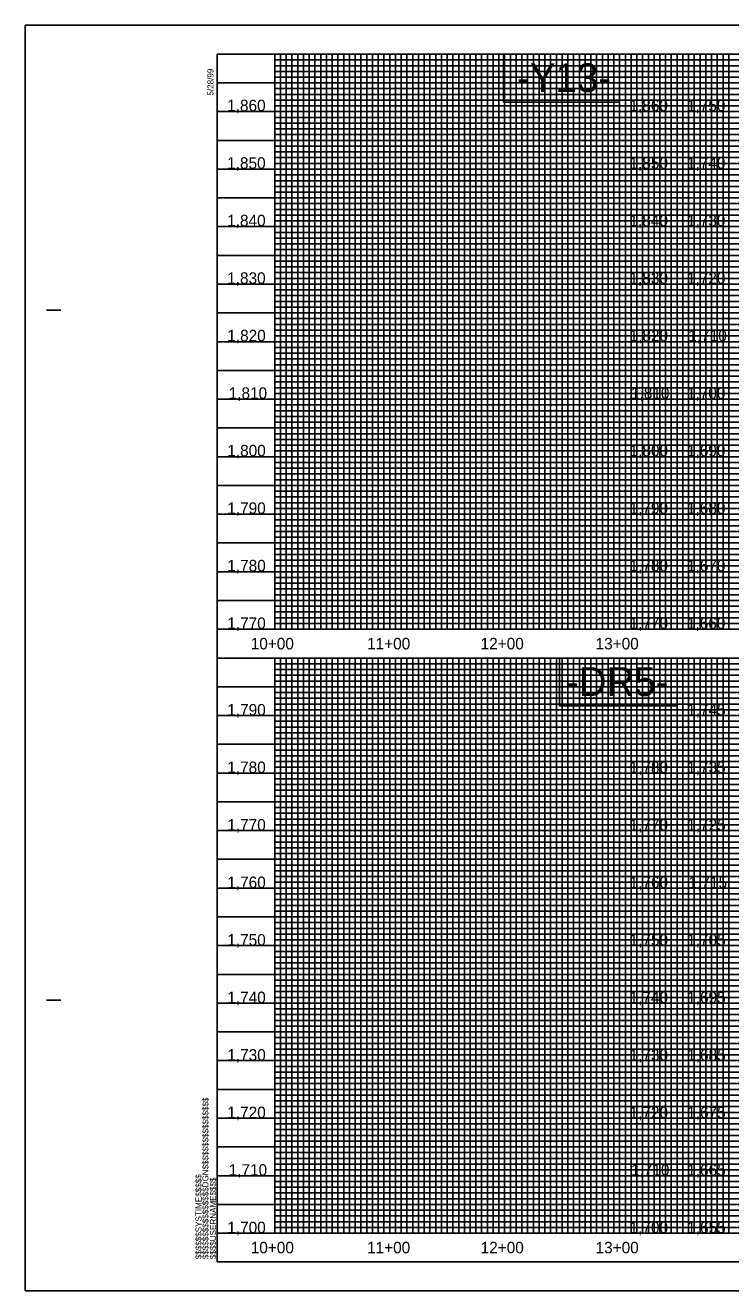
# Model space of a CAD drawing. Extents: x 505602 to 507286, y 483109 to 484209.
# Drawn here: x 505602 to 506216, y 483109 to 484209 of the extents above; entities that cross this region are included whole.
import ezdxf

# ---------------------------------------------------------------- set-up
doc = ezdxf.new("R2010")
doc.units = 0
for name, color, linetype in [('Exist Vertical Profile Vertical Axis Label', 7, 'Continuous'), ('Old_Level_1', 7, 'Continuous'), ('Prop Grid Mask', 7, 'Continuous'), ('Sheet Layout Profile Border Port 1', 7, 'Continuous'), ('Sheet Layout Profile Border Port 2', 7, 'Continuous'), ('Sheet Plot Border Outside CELL', 7, 'Continuous'), ('Sheet Profile CELL', 7, 'Continuous'), ('Sheet Profile Grid Major CELL', 7, 'Continuous'), ('Sheet Profile Grid Middle CELL', 7, 'Continuous'), ('Sheet Profile Grid Minor CELL', 7, 'Continuous')]:
    doc.layers.add(name, color=color, linetype=linetype)

msp = doc.modelspace()

# ---------------------------------------------------------------- linework, layer by layer
at = {"layer": 'Prop Grid Mask'}
for points in [[(506119.1, 484183.7), (506018.1, 484183.7), (506018.1, 484142), (506119.1, 484142)], [(506169.1, 483658.7), (506066.8, 483658.7), (506066.8, 483617), (506169.1, 483617)]]:
    msp.add_lwpolyline(points, close=True, dxfattribs=at)
at = {"layer": 'Sheet Layout Profile Border Port 1'}
msp.add_lwpolyline([(505769.1, 484183.7), (506169.1, 484183.7), (506169.1, 483683.7), (505769.1, 483683.7)], close=True, dxfattribs=at)
at = {"layer": 'Sheet Layout Profile Border Port 2'}
for points in [[(505819.1, 483658.7), (506169.1, 483658.7), (506169.1, 483158.7), (505819.1, 483158.7)], [(506169.1, 483658.7), (507219.1, 483658.7), (507219.1, 483158.7), (506169.1, 483158.7)]]:
    msp.add_lwpolyline(points, close=True, dxfattribs=at)
at = {"layer": 'Sheet Plot Border Outside CELL'}
msp.add_lwpolyline([(505602.1, 483108.7), (507286.1, 483108.7), (507286.1, 484208.7), (505602.1, 484208.7)], close=True, dxfattribs=at)
at = {"layer": 'Sheet Profile CELL'}
for p, q in [((506169.1, 483683.7), (506169.1, 484183.7)), ((505620.6, 483961.2), (505633.1, 483961.2)), ((505769.1, 483683.7), (507269.1, 483683.7)), ((505769.1, 483658.7), (507269.1, 483658.7)), ((506169.1, 483158.7), (506169.1, 483658.7)), ((505620.6, 483361.2), (505633.1, 483361.2)), ((507269.1, 483158.7), (505769.1, 483158.7)), ((505769.1, 483133.7), (507269.1, 483133.7)), ((505769.1, 483133.7), (505769.1, 483133.7)), ((505769.1, 483133.7), (505769.1, 483133.7)), ((505769.1, 483133.7), (505769.1, 483133.7)), ((505769.1, 483133.7), (505769.1, 483133.7)), ((505769.1, 483133.7), (505769.1, 483133.7)), ((505769.1, 483133.7), (505769.1, 483133.7)), ((505769.1, 483133.7), (505769.1, 483133.7))]:
    msp.add_line(p, q, dxfattribs=at)
msp.add_lwpolyline([(507269.1, 484183.7), (505769.1, 484183.7), (505769.1, 483133.7), (507269.1, 483133.7)], close=True, dxfattribs=at)
msp.add_lwpolyline([(505806.6, 483133.7), (505806.6, 483133.7)], dxfattribs=at)
at = {"layer": 'Sheet Profile Grid Major CELL'}
for points in [[(505819.1, 484183.7), (505819.1, 483683.7), (505869.1, 483683.7), (505869.1, 484183.7), (505919.1, 484183.7), (505919.1, 483683.7), (505969.1, 483683.7), (505969.1, 484183.7), (506019.1, 484183.7), (506019.1, 483683.7), (506069.1, 483683.7), (506069.1, 484183.7), (506119.1, 484183.7), (506119.1, 483683.7), (506169.1, 483683.7), (506169.1, 484183.7), (506219.1, 484183.7)], [(505769.1, 484133.7), (507069.1, 484133.7)], [(507069.1, 484083.7), (505769.1, 484083.7), (505769.1, 484033.7), (507069.1, 484033.7)], [(507269.1, 483983.7), (505769.1, 483983.7), (505769.1, 483933.7), (507269.1, 483933.7)], [(507269.1, 483883.7), (505769.1, 483883.7), (505769.1, 483833.7), (507269.1, 483833.7)], [(507269.1, 483783.7), (505769.1, 483783.7), (505769.1, 483783.7), (505769.1, 483733.7), (507269.1, 483733.7)], [(505769.1, 483658.7), (505769.1, 483158.7), (505819.1, 483158.7), (505819.1, 483658.7), (505869.1, 483658.7), (505869.1, 483158.7), (505919.1, 483158.7), (505919.1, 483658.7), (505969.1, 483658.7), (505969.1, 483158.7), (506019.1, 483158.7), (506019.1, 483658.7), (506069.1, 483658.7), (506069.1, 483158.7), (506119.1, 483158.7), (506119.1, 483658.7), (506169.1, 483658.7), (506169.1, 483158.7), (506219.1, 483158.7)], [(505819.1, 483658.7), (505819.1, 483158.7), (505869.1, 483158.7), (505869.1, 483658.7), (505919.1, 483658.7), (505919.1, 483158.7), (505969.1, 483158.7), (505969.1, 483658.7), (506019.1, 483658.7), (506019.1, 483158.7), (506069.1, 483158.7), (506069.1, 483658.7), (506119.1, 483658.7), (506119.1, 483158.7), (506169.1, 483158.7), (506169.1, 483658.7), (506219.1, 483658.7)], [(507269.1, 483608.7), (505769.1, 483608.7)], [(507269.1, 483558.7), (505769.1, 483558.7), (505769.1, 483508.7), (507269.1, 483508.7)], [(507269.1, 483458.7), (505769.1, 483458.7), (505769.1, 483408.7), (507269.1, 483408.7)], [(507269.1, 483358.7), (505769.1, 483358.7), (505769.1, 483308.7), (507269.1, 483308.7)], [(507269.1, 483258.7), (505769.1, 483258.7), (505769.1, 483258.7), (505769.1, 483208.7), (507269.1, 483208.7)], [(507269.1, 483158.7), (505769.1, 483158.7)]]:
    msp.add_lwpolyline(points, dxfattribs=at)
at = {"layer": 'Sheet Profile Grid Middle CELL'}
msp.add_line((505769.1, 484158.7), (507069, 484158.7), dxfattribs=at)
msp.add_line((505769.1, 484158.7), (507069, 484158.7), dxfattribs=at)
for points in [[(505844.1, 484183.7), (505844.1, 483683.7), (505894.1, 483683.7), (505894.1, 484183.7), (505944.1, 484183.7), (505944.1, 483683.7), (505994.1, 483683.7), (505994.1, 484183.7), (506044.1, 484183.7), (506044.1, 483683.7), (506094.1, 483683.7), (506094.1, 484183.7), (506144.1, 484183.7), (506144.1, 483683.7), (506194.1, 483683.7), (506194.1, 484183.7), (506244.1, 484183.7)], [(507069.1, 484108.7), (505769.1, 484108.7), (505769.1, 484058.7), (507069.1, 484058.7)], [(507269.1, 484008.7), (505769.1, 484008.7), (505769.1, 483958.7), (507094.1, 483958.7)], [(507269.1, 483908.7), (505769.1, 483908.7), (505769.1, 483858.7), (507269.1, 483858.7)], [(507269.1, 483808.7), (505769.1, 483808.7), (505769.1, 483758.7), (507269.1, 483758.7)], [(507269.1, 483708.7), (505769.1, 483708.7)], [(505794.1, 483658.7), (505844.1, 483658.7), (505844.1, 483158.7), (505894.1, 483158.7), (505894.1, 483658.7), (505944.1, 483658.7), (505944.1, 483158.7), (505994.1, 483158.7), (505994.1, 483658.7), (506044.1, 483658.7), (506044.1, 483158.7), (506094.1, 483158.7), (506094.1, 483658.7), (506144.1, 483658.7), (506144.1, 483158.7), (506194.1, 483158.7), (506194.1, 483658.7), (506244.1, 483658.7)], [(505769.1, 483633.7), (507269.1, 483633.7)], [(507269.1, 483583.7), (505769.1, 483583.7), (505769.1, 483533.7), (507269.1, 483533.7)], [(507269.1, 483483.7), (505769.1, 483483.7), (505769.1, 483433.7), (507269.1, 483433.7)], [(507269.1, 483383.7), (505769.1, 483383.7), (505769.1, 483333.7), (507269.1, 483333.7)], [(507269.1, 483283.7), (505769.1, 483283.7), (505769.1, 483233.7), (507269.1, 483233.7)], [(507269.1, 483183.7), (505769.1, 483183.7)]]:
    msp.add_lwpolyline(points, dxfattribs=at)
at = {"layer": 'Sheet Profile Grid Minor CELL'}
for p, q in [((505819.1, 484178.7), (507069.1, 484178.7)), ((505819.1, 484173.7), (505819.1, 484173.7)), ((507069.1, 484173.7), (505819.1, 484173.4)), ((505819.1, 484168.7), (507069.1, 484168.7)), ((507069, 484048.7), (505819.1, 484048.7)), ((507069.1, 484043.7), (505819.1, 484043.7)), ((507069.1, 484038.7), (505819.1, 484038.7)), ((505819.1, 484028.7), (507069.1, 484028.7)), ((507069.1, 484023.7), (505819.1, 484023.7)), ((505819.1, 484018.7), (507219.1, 484018.7)), ((507219.1, 483998.7), (505819.1, 483998.7)), ((505819.1, 483993.7), (507219.1, 483993.7)), ((507219.1, 483973.7), (505819.1, 483973.7)), ((505819.1, 483968.7), (507219.1, 483968.7)), ((507219.1, 483948.7), (505819.1, 483948.7)), ((505819.1, 483943.7), (507219.1, 483943.7)), ((507219.1, 483938.7), (505819.1, 483938.7)), ((505819.1, 483928.7), (507219.1, 483928.7)), ((507219.1, 483923.7), (505819.1, 483923.7)), ((505819.1, 483918.7), (507219.1, 483918.7)), ((507219.1, 483913.7), (505819.1, 483913.7)), ((505819.1, 483903.7), (507219.1, 483903.7)), ((507219.1, 483898.7), (505819.1, 483898.7)), ((505819.1, 483893.7), (507219.1, 483893.7)), ((507219.1, 483888.7), (505819.1, 483888.7)), ((505819.1, 483878.7), (507219.1, 483878.7)), ((507219.1, 483873.7), (505819.1, 483873.7)), ((505819.1, 483868.7), (507219.1, 483868.7)), ((507219.1, 483863.7), (505819.1, 483863.7)), ((505819.1, 483853.7), (507219.1, 483853.7)), ((507219.1, 483848.7), (505819.1, 483848.7)), ((505819.1, 483843.7), (507219.1, 483843.7)), ((507219.1, 483838.7), (505819.1, 483838.7)), ((505819.1, 483828.7), (507219.1, 483828.7)), ((507219.1, 483823.7), (505819.1, 483823.7)), ((505819.1, 483818.7), (507219.1, 483818.7)), ((507219.1, 483813.7), (505819.1, 483813.7)), ((505819.1, 483803.7), (507219.1, 483803.7)), ((507219.1, 483798.7), (505819.1, 483798.7)), ((507219.1, 483793.7), (505819.1, 483793.7)), ((507219.1, 483788.7), (505819.1, 483788.7)), ((505819.1, 483778.7), (507219.1, 483778.7)), ((507219.1, 483773.7), (505819.1, 483773.7)), ((505819.1, 483768.7), (507219.1, 483768.7)), ((507219.1, 483763.7), (505819.1, 483763.7)), ((505819.1, 483753.7), (507219.1, 483753.7)), ((507219.1, 483748.7), (505819.1, 483748.7)), ((505819.1, 483743.7), (507219.1, 483743.7)), ((507219.1, 483738.7), (505819.1, 483738.7)), ((505819.1, 483728.7), (507219.1, 483728.7)), ((507219.1, 483723.7), (505819.1, 483723.7)), ((505819.1, 483718.7), (507219.1, 483718.7)), ((507219.1, 483713.7), (505819.1, 483713.7)), ((505819.1, 483703.7), (507219.1, 483703.7)), ((507219.1, 483698.7), (505819.1, 483698.7)), ((505819.1, 483693.7), (507219.1, 483693.7)), ((505819.1, 483653.7), (507219.1, 483653.7)), ((507219.1, 483648.7), (505819.1, 483648.7)), ((505819.1, 483643.7), (507219.1, 483643.7)), ((507219.1, 483638.7), (505819.1, 483638.7)), ((505819.1, 483628.7), (507219.1, 483628.7)), ((507219.1, 483623.7), (505819.1, 483623.7)), ((505819.1, 483618.7), (507219.1, 483618.7)), ((507219.1, 483613.7), (505819.1, 483613.7)), ((505819.1, 483603.7), (507219.1, 483603.7)), ((507219.1, 483598.7), (505819.1, 483598.7)), ((505819.1, 483593.7), (507219.1, 483593.7)), ((507219.1, 483588.7), (505819.1, 483588.7)), ((505819.1, 483578.7), (507219.1, 483578.7)), ((507219.1, 483573.7), (505819.1, 483573.7)), ((505819.1, 483568.7), (507219.1, 483568.7)), ((507219.1, 483563.7), (505819.1, 483563.7)), ((505819.1, 483553.7), (507219.1, 483553.7)), ((507219.1, 483548.7), (505819.1, 483548.7)), ((505819.1, 483543.7), (507219.1, 483543.7)), ((507219.1, 483538.7), (505819.1, 483538.7)), ((505819.1, 483528.7), (507219.1, 483528.7)), ((507219.1, 483523.7), (505819.1, 483523.7)), ((505819.1, 483518.7), (507219.1, 483518.7)), ((507219.1, 483513.7), (505819.1, 483513.7)), ((505819.1, 483503.7), (507219.1, 483503.7)), ((507219.1, 483498.7), (505819.1, 483498.7)), ((505819.1, 483493.7), (507219.1, 483493.7)), ((507219.1, 483488.7), (505819.1, 483488.7)), ((505819.1, 483478.7), (507219.1, 483478.7)), ((507219.1, 483473.7), (505819.1, 483473.7)), ((505819.1, 483468.7), (507219.1, 483468.7)), ((507219.1, 483463.7), (505819.1, 483463.9)), ((505819.1, 483453.7), (507219.1, 483453.7)), ((507219.1, 483448.7), (505819.1, 483448.7)), ((505819.1, 483443.7), (507219.1, 483443.7)), ((507219.1, 483438.7), (505819.1, 483438.7)), ((505819.1, 483428.7), (507219.1, 483428.7)), ((507219.1, 483423.7), (505819.1, 483423.7)), ((505819.1, 483418.7), (507219.1, 483418.7)), ((507219.1, 483413.7), (505819.1, 483413.7)), ((505819.1, 483403.7), (507219.1, 483403.7)), ((507219.1, 483398.7), (505819.1, 483398.7)), ((505819.1, 483393.7), (507219.1, 483393.7)), ((507219.1, 483388.7), (505819.1, 483388.7)), ((505819.1, 483378.7), (507219.1, 483378.7)), ((507219.1, 483373.7), (505819.1, 483373.7)), ((505819.1, 483368.7), (507219.1, 483368.7)), ((507219.1, 483363.7), (505819.1, 483363.7)), ((505819.1, 483353.7), (507219.1, 483353.7)), ((507219.1, 483348.7), (505819.1, 483348.7)), ((505819.1, 483343.7), (507219.1, 483343.7)), ((507219.1, 483338.7), (505819.1, 483338.7)), ((505819.1, 483328.7), (507219.1, 483328.7)), ((507219.1, 483323.7), (505819.1, 483323.7)), ((505819.1, 483318.7), (507219.1, 483318.7)), ((507219.1, 483313.7), (505819.1, 483313.7)), ((505819.1, 483303.7), (507219.1, 483303.7)), ((507219.1, 483298.7), (505819.1, 483298.7)), ((505819.1, 483293.7), (507219.1, 483293.7)), ((507219.1, 483288.7), (505819.1, 483288.7)), ((505819.1, 483278.7), (507219.1, 483278.7)), ((507219.1, 483273.7), (505819.1, 483273.7)), ((505819.1, 483268.7), (507219.1, 483268.7)), ((507219.1, 483263.7), (505819.1, 483263.7)), ((505819.1, 483253.7), (507219.1, 483253.7)), ((507219.1, 483248.7), (505819.1, 483248.7)), ((505819.1, 483243.7), (507219.1, 483243.7)), ((507219.1, 483238.7), (505819.1, 483238.7)), ((505819.1, 483228.7), (507219.1, 483228.7)), ((507219.1, 483223.7), (505819.1, 483223.7)), ((505819.1, 483218.7), (507219.1, 483218.7)), ((507219.1, 483213.7), (505819.1, 483213.7)), ((505819.1, 483203.7), (507219.1, 483203.7)), ((507219.1, 483198.7), (505819.1, 483198.7)), ((505819.1, 483193.7), (507219.1, 483193.7)), ((507219.1, 483188.7), (505819.1, 483188.7)), ((505819.1, 483178.7), (507219.1, 483178.7)), ((507219.1, 483173.7), (505819.1, 483173.7)), ((505819.1, 483168.7), (507219.1, 483168.7)), ((505819.1, 483163.7), (507219.1, 483163.7))]:
    msp.add_line(p, q, dxfattribs=at)
for points in [[(505824.1, 484183.7), (505824.1, 483683.7), (505829.1, 483683.7), (505829.1, 484183.7), (505834.1, 484183.7), (505834.1, 483683.7), (505839.1, 483683.7), (505839.1, 484183.7), (505849.1, 484183.7), (505849.1, 483683.7), (505854.1, 483683.7), (505854.1, 484183.7), (505859.1, 484183.7), (505859.1, 483683.7), (505864.1, 483683.7), (505874.1, 483683.7), (505879.1, 483683.7), (505879.1, 484183.7), (505884.1, 484183.7), (505884.1, 483683.7), (505889.1, 483683.7), (505889.1, 484183.7), (505899.1, 484183.7), (505899.1, 483683.7), (505904.1, 483683.7), (505904.1, 484183.7), (505909.1, 484183.7), (505909.1, 483683.7), (505914.1, 483683.7), (505914.1, 484183.7), (505924.1, 484183.7), (505924.1, 483683.7), (505929.1, 483683.7), (505929.1, 484183.7), (505934.1, 484183.7), (505934.1, 483683.7), (505939.1, 483683.7), (505939.1, 484183.7), (505949.1, 484183.7), (505949.1, 483683.7), (505954.1, 483683.7), (505954.1, 484183.7), (505959.1, 484183.7), (505959.1, 483683.7), (505964.1, 483683.7), (505964.1, 484183.7), (505974.1, 484183.7), (505974.1, 483683.7), (505979.1, 483683.7), (505979.1, 484183.7), (505984.1, 484183.7), (505984.1, 483683.7), (505989.1, 483683.7), (505989.1, 484183.7), (505999.1, 484183.7), (505999.1, 483683.7), (506004.1, 483683.7), (506004.1, 484183.7), (506009.1, 484183.7), (506009.1, 483683.7), (506014.1, 483683.7), (506014.1, 484183.7), (506024.1, 484183.7), (506024.1, 483683.7), (506029.1, 483683.7), (506029.1, 484183.7), (506034.1, 484183.7), (506034.1, 483683.7)], [(505864.1, 483683.7), (505864.1, 484183.7), (505874.1, 484183.7), (505874.1, 483683.7)], [(506034.1, 483683.7), (506039.1, 483683.7), (506039.1, 484183.7), (506049.1, 484183.7), (506049.1, 483683.7), (506054.1, 483683.7), (506054.1, 484183.7), (506059.1, 484183.7), (506059.1, 483683.7), (506064.1, 483683.7), (506064.1, 484183.7), (506074.1, 484183.7), (506074.1, 483683.7), (506079.1, 483683.7), (506079.1, 484183.7), (506084.1, 484183.7), (506084.1, 483683.7), (506089.1, 483683.7), (506089.1, 484183.7), (506099.1, 484183.7), (506099.1, 483683.7), (506104.1, 483683.7), (506104.1, 484183.7), (506109.1, 484183.7), (506109.1, 483683.7), (506114.1, 483683.7), (506114.1, 484183.7), (506124.1, 484183.7), (506124.1, 483683.7), (506129.1, 483683.7), (506129.1, 484183.7), (506134.1, 484183.7), (506134.1, 483683.7), (506139.1, 483683.7), (506139.1, 484183.7), (506149.1, 484183.7), (506149.1, 483683.7), (506154.1, 483683.7), (506154.1, 484183.7), (506159.1, 484183.7), (506159.1, 483683.7), (506164.1, 483683.7), (506164.1, 484183.7), (506174.1, 484183.7), (506174.1, 483683.7), (506179.1, 483683.7), (506179.1, 484183.7), (506184.1, 484183.7), (506184.1, 483683.7), (506189.1, 483683.7), (506189.1, 484183.7), (506199.1, 484183.7), (506199.1, 483683.7), (506204.1, 483683.7), (506204.1, 484183.7), (506209.1, 484183.7), (506209.1, 483683.7), (506214.1, 483683.7), (506214.1, 484183.7), (506224.1, 484183.7)], [(507069.1, 484163.7), (505819.1, 484163.7), (505819.1, 484153.7), (507069.1, 484153.7)], [(507069, 484148.7), (505819.1, 484148.7), (505819.1, 484143.7), (507069.1, 484143.7)], [(507069.1, 484138.7), (505819.1, 484138.7), (505819.1, 484128.7), (507069.1, 484128.7)], [(507069.1, 484123.7), (505819.1, 484123.7), (505819.1, 484118.7), (507069.1, 484118.7)], [(507069.1, 484113.7), (505819.1, 484113.7), (505819.1, 484103.7), (507069.1, 484103.7)], [(507069.1, 484098.7), (505819.1, 484098.7), (505819.1, 484093.7), (507069.1, 484093.7)], [(507069.1, 484088.7), (505819.1, 484088.7), (505819.1, 484078.7), (507069.1, 484078.7)], [(507069.1, 484073.6), (505819.2, 484073.6), (505819.2, 484068.7), (507069.1, 484068.7)], [(507069.1, 484063.7), (505819.1, 484063.7), (505819.1, 484053.7), (507069.1, 484053.7)], [(507219.1, 484013.7), (505819.1, 484013.7), (505819.1, 484003.7), (507219.1, 484003.7)], [(507219.1, 483988.7), (505819.1, 483988.7), (505819.1, 483978.7), (507219.1, 483978.7)], [(507219.1, 483963.7), (505819.1, 483963.7), (505819.1, 483953.7), (507219.1, 483953.7)], [(507219.1, 483688.7), (505819.1, 483688.7)], [(505819.1, 483658.7), (505824.1, 483658.7), (505824.1, 483158.7), (505829.1, 483158.7), (505829.1, 483658.7), (505834.1, 483658.7), (505834.1, 483158.7), (505839.1, 483158.7), (505839.1, 483658.7), (505849.1, 483658.7), (505849.1, 483158.7), (505854.1, 483158.7), (505854.1, 483658.7), (505859.1, 483658.7), (505859.1, 483158.7), (505864.1, 483158.7), (505874.1, 483158.7), (505879.1, 483158.7), (505879.1, 483658.7), (505884.1, 483658.7), (505884.1, 483158.7), (505889.1, 483158.7), (505889.1, 483658.7), (505899.1, 483658.7), (505899.1, 483158.7), (505904.1, 483158.7), (505904.1, 483658.7), (505909.1, 483658.7), (505909.1, 483158.7), (505914.1, 483158.7), (505914.1, 483658.7), (505924.1, 483658.7), (505924.1, 483158.7), (505929.1, 483158.7), (505929.1, 483658.7), (505934.1, 483658.7), (505934.1, 483158.7), (505939.1, 483158.7), (505939.1, 483658.7), (505949.1, 483658.7), (505949.1, 483158.7), (505954.1, 483158.7), (505954.1, 483658.7), (505959.1, 483658.7), (505959.1, 483158.7), (505964.1, 483158.7), (505964.1, 483658.7), (505974.1, 483658.7), (505974.1, 483158.7), (505979.1, 483158.7), (505979.1, 483658.7), (505984.1, 483658.7), (505984.1, 483158.7), (505989.1, 483158.7), (505989.1, 483658.7), (505999.1, 483658.7), (505999.1, 483158.7), (506004.1, 483158.7), (506004.1, 483658.7), (506009.1, 483658.7), (506009.1, 483158.7), (506014.1, 483158.7), (506014.1, 483658.7), (506024.1, 483658.7), (506024.1, 483158.7), (506029.1, 483158.7), (506029.1, 483658.7), (506034.1, 483658.7), (506034.1, 483158.7)], [(505864.1, 483158.7), (505864.1, 483658.7), (505874.1, 483658.7), (505874.1, 483158.7)], [(506034.1, 483158.7), (506039.1, 483158.7), (506039.1, 483658.7), (506049.1, 483658.7), (506049.1, 483158.7), (506054.1, 483158.7), (506054.1, 483658.7), (506059.1, 483658.7), (506059.1, 483158.7), (506064.1, 483158.7), (506064.1, 483658.7), (506074.1, 483658.7), (506074.1, 483158.7), (506079.1, 483158.7), (506079.1, 483658.7), (506084.1, 483658.7), (506084.1, 483158.7), (506089.1, 483158.7), (506089.1, 483658.7), (506099.1, 483658.7), (506099.1, 483158.7), (506104.1, 483158.7), (506104.1, 483658.7), (506109.1, 483658.7), (506109.1, 483158.7), (506114.1, 483158.7), (506114.1, 483658.7), (506124.1, 483658.7), (506124.1, 483158.7), (506129.1, 483158.7), (506129.1, 483658.7), (506134.1, 483658.7), (506134.1, 483158.7), (506139.1, 483158.7), (506139.1, 483658.7), (506149.1, 483658.7), (506149.1, 483158.7), (506154.1, 483158.7), (506154.1, 483658.7), (506159.1, 483658.7), (506159.1, 483158.7), (506164.1, 483158.7), (506164.1, 483658.7), (506174.1, 483658.7), (506174.1, 483158.7), (506179.1, 483158.7), (506179.1, 483658.7), (506184.1, 483658.7), (506184.1, 483158.7), (506189.1, 483158.7), (506189.1, 483658.7), (506199.1, 483658.7), (506199.1, 483158.7), (506204.1, 483158.7), (506204.1, 483658.7), (506209.1, 483658.7), (506209.1, 483158.7), (506214.1, 483158.7), (506214.1, 483658.7), (506224.1, 483658.7)]]:
    msp.add_lwpolyline(points, dxfattribs=at)

# ---------------------------------------------------------------- texts
at = {"layer": 'Exist Vertical Profile Vertical Axis Label'}
for s, p in [('1,860', (505777.7, 484134)), ('1,860', (506127.7, 484134)), ('1,750', (506177.7, 484134)), ('1,850', (505777.7, 484084)), ('1,850', (506127.7, 484084)), ('1,740', (506177.7, 484084)), ('1,840', (505777.7, 484034)), ('1,840', (506127.7, 484034)), ('1,730', (506177.7, 484034)), ('1,830', (505777.7, 483984)), ('1,830', (506127.7, 483984)), ('1,720', (506177.7, 483984)), ('1,820', (505777.8, 483934)), ('1,820', (506127.8, 483934)), ('1,710', (506178.9, 483934)), ('1,810', (505779, 483884)), ('1,810', (506129, 483884)), ('1,700', (506177.7, 483884)), ('1,800', (505777.8, 483834)), ('1,800', (506127.8, 483834)), ('1,690', (506177.7, 483834)), ('1,790', (505777.8, 483784)), ('1,790', (506127.8, 483784)), ('1,680', (506177.7, 483784)), ('1,780', (505777.8, 483734)), ('1,780', (506127.8, 483734)), ('1,670', (506177.7, 483734)), ('1,770', (505777.8, 483684)), ('1,770', (506127.8, 483684)), ('1,660', (506177.7, 483684)), ('10+00', (505798.2, 483666.2)), ('11+00', (505899.4, 483666.2)), ('12+00', (505998.2, 483666.2)), ('13+00', (506098.2, 483666.2)), ('1,790', (505777.8, 483608.7)), ('1,745', (506177.9, 483608.7)), ('1,780', (505777.8, 483558.7)), ('1,780', (506127.8, 483558.7)), ('1,735', (506177.9, 483558.7)), ('1,770', (505777.8, 483508.7)), ('1,770', (506127.8, 483508.7)), ('1,725', (506177.9, 483508.7)), ('1,760', (505777.8, 483458.7)), ('1,760', (506127.8, 483458.7)), ('1,715', (506179.1, 483458.7)), ('1,750', (505777.8, 483408.7)), ('1,750', (506127.8, 483408.7)), ('1,705', (506177.9, 483408.7)), ('1,740', (505777.8, 483358.7)), ('1,740', (506127.8, 483358.7)), ('1,695', (506177.9, 483358.7)), ('1,730', (505777.8, 483308.7)), ('1,730', (506127.8, 483308.7)), ('1,685', (506177.9, 483308.7)), ('1,720', (505777.8, 483258.7)), ('1,720', (506127.8, 483258.7)), ('1,675', (506177.9, 483258.7)), ('1,710', (505779, 483208.7)), ('1,710', (506129, 483208.7)), ('1,665', (506177.9, 483208.7)), ('1,700', (505777.8, 483158.7)), ('1,700', (506127.8, 483158.7)), ('1,655', (506177.9, 483158.7)), ('10+00', (505798.2, 483141.2)), ('11+00', (505899.4, 483141.2)), ('12+00', (505998.2, 483141.2)), ('13+00', (506098.2, 483141.2))]:
    msp.add_text(s, height=10, dxfattribs=at).set_placement(p)
at = {"layer": 'Old_Level_1'}
for s, p in [('-Y13-', (506029.9, 484150.7)), ('-DR5-', (506072.4, 483625.7))]:
    msp.add_text(s, height=25, dxfattribs=at).set_placement(p)
at = {"layer": 'Sheet Profile CELL'}
for s, p in [('5/28/99', (505765.8, 484147.6)), ('$$$$$$$$$$$$$$$$DGN$$$$$$$$$$$$$$$$', (505761.4, 483136.1)), ('$$$$$$SYSTIME$$$$$', (505755.4, 483136.1)), ('$$$$USERNAME$$$$', (505768, 483136.1))]:
    msp.add_text(s, height=5.25, rotation=90, dxfattribs=at).set_placement(p)

doc.saveas('drawing.dxf')
